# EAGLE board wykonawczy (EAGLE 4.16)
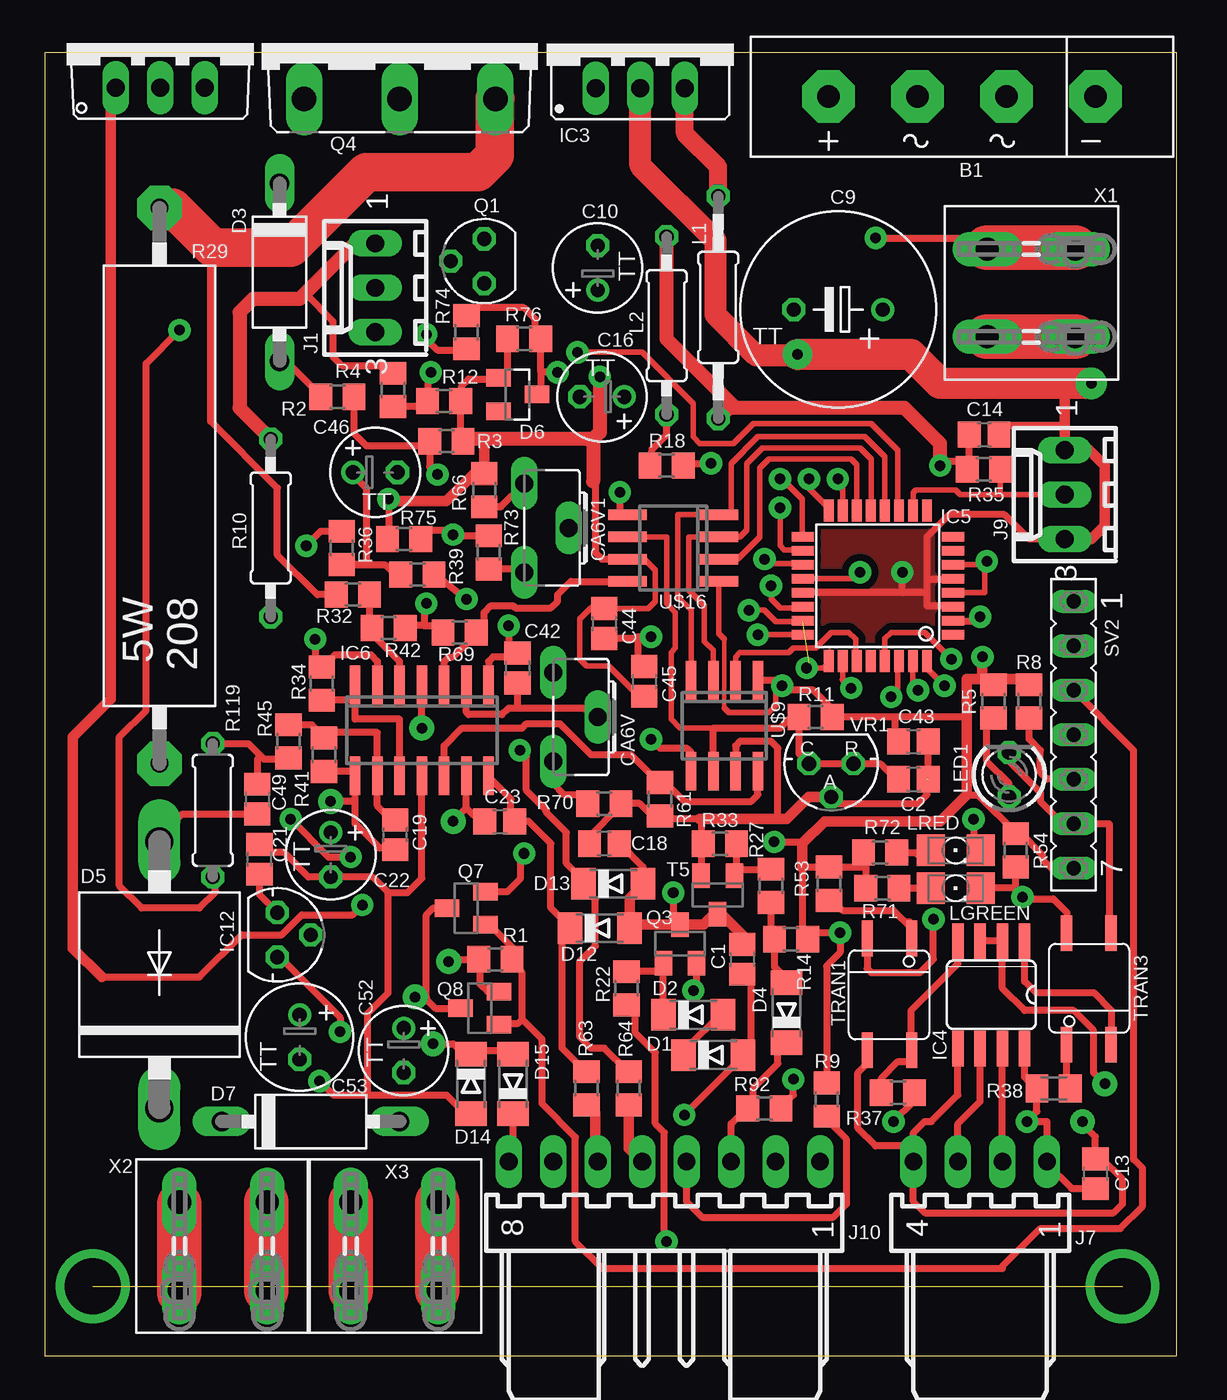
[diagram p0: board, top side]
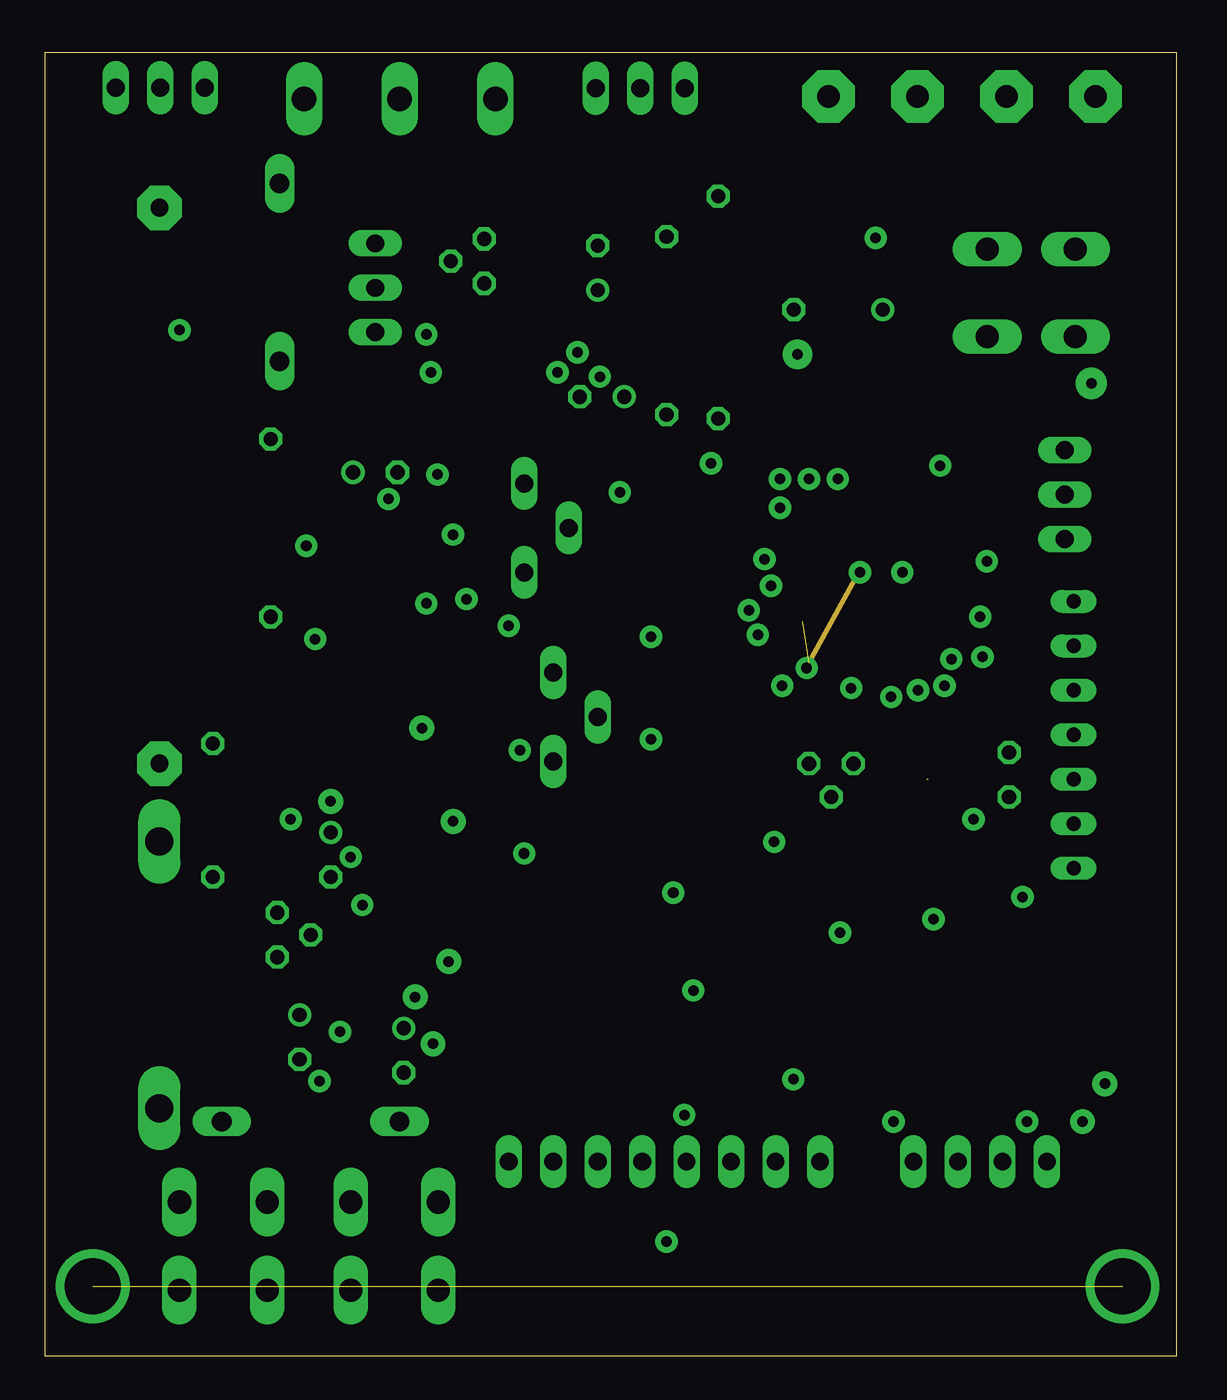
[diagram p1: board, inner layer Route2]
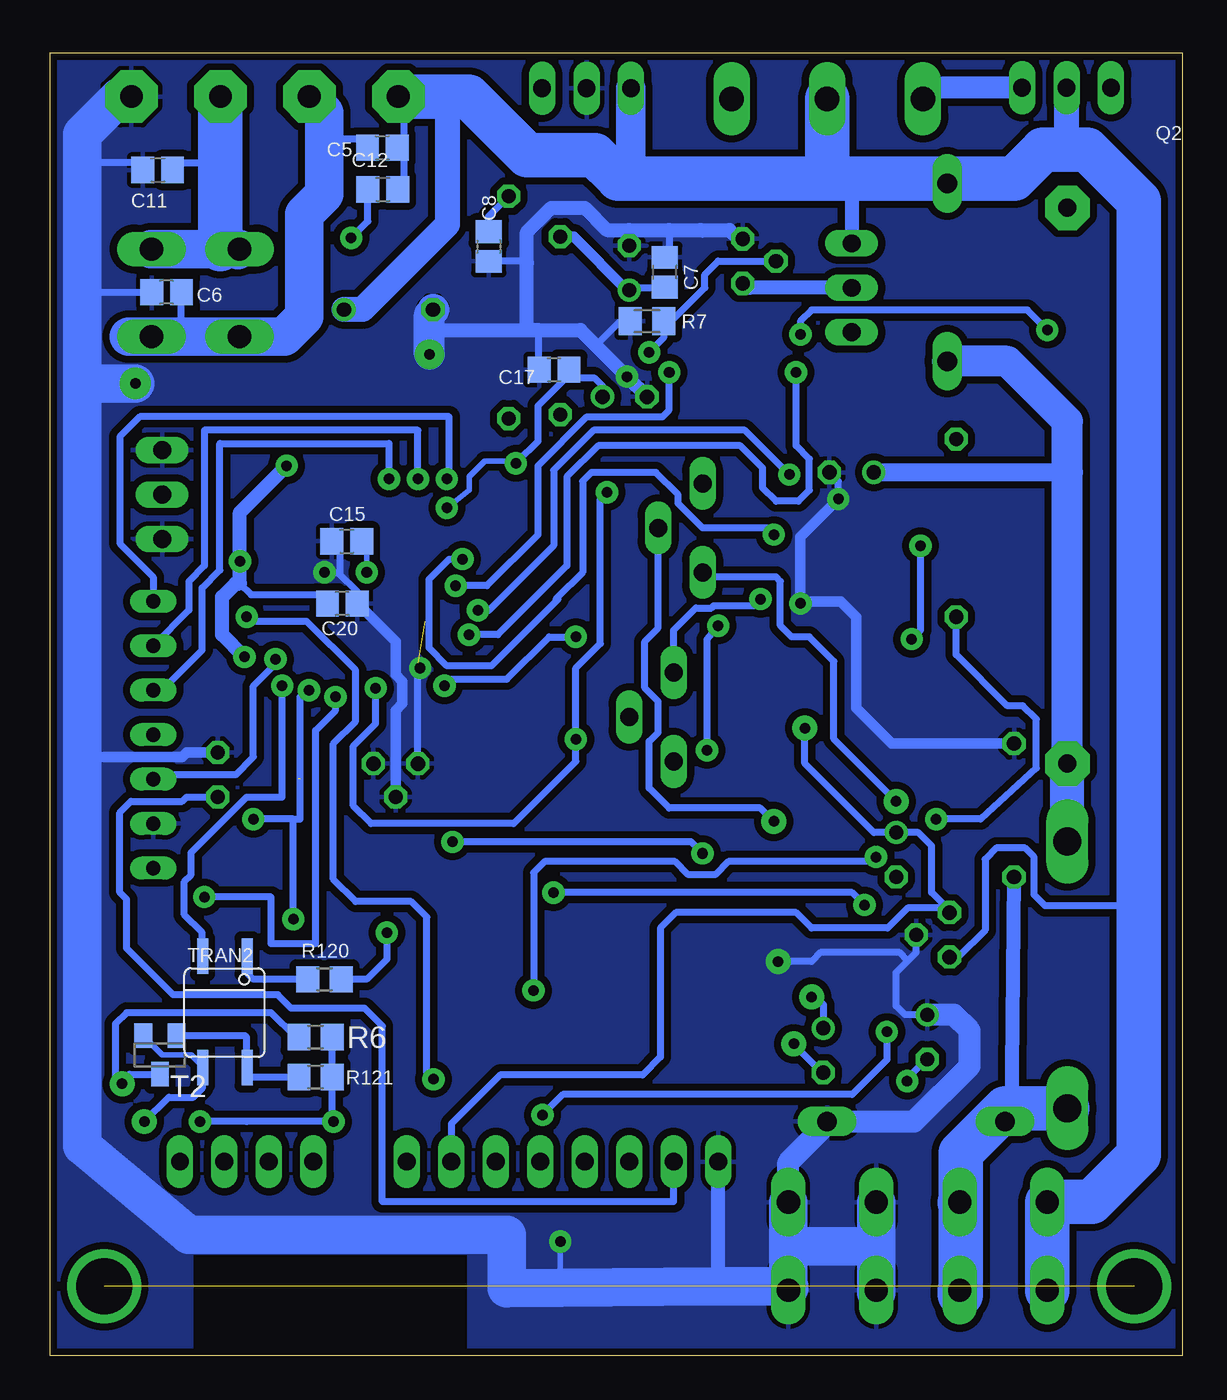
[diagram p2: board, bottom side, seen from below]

Size 64.62 x 74.42 mm. Coordinates in mm from the lower left corner, seen from the top.
Outline: 0,0 64.62,0 64.62,74.42 0,74.42 0,0
Copper layers (1*16): Top 0.035mm / dielectric 1.5mm / Bottom 0.035mm
Design rules "default": minimum track width 10mil, minimum drill 20mil, track to track 8mil, track to pad 8mil, pad to pad 8mil, via to via 8mil, smd to smd 8mil, copper to edge 1mil, drill to drill 8mil, minimum pad ring 10mil, minimum via ring 8mil, stop-mask expansion 4mil, vias tented up to drill 0mil, thermal gap 10mil

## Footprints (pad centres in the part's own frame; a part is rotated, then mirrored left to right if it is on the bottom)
2KBB_R2 = drill 1.3 pad 3 octagon: + -7.62,0; - 7.62,0; ~1 -2.54,0; ~2 2.54,0
C0805 = smd 1.3 x 1.5: 1 -0.85,0; 2 0.85,0
TT5D11 = drill 0.813 round: + -2.54,0 | drill 0.813 octagon: - 2.54,0
TT2D5 = drill 0.813 round: + -1.27,0 | drill 0.813 octagon: - 1.27,0
TT2D6 = drill 0.813 round: + -1.27,0 | drill 0.813 octagon: - 1.27,0
CA6H = drill 1.016 long: A -2.54,0; E 2.54,0; S 0,2.54
MINIMELF = smd 1.4 x 1.8: A 1.7,0; C -1.7,0
P1-10 = drill 1.118 long: A 5.08,0; C -5.08,0
P6-15 = drill 1.6 long: A 7.62,0; C -7.62,0
SOT23 = smd 1 x 1.4: 1 -0.95,-1.1; 2 0.95,-1.1; 3 0,1.1
78XXS = drill 1.016 long: GND 0,-2.54; IN -2.54,-2.54; OUT 2.54,-2.54
SO08 = smd 0.66 x 2.032: 1 -1.905,-3.073; 2 -0.635,-3.073; 3 0.635,-3.073; 4 1.905,-3.073; 5 1.905,3.073; 6 0.635,3.073; 7 -0.635,3.073; 8 -1.905,3.073
TQFP32-08 = smd 1.27 x 0.559: 1 -4.293,2.8; 2 -4.293,2; 3 -4.293,1.2; 4 -4.293,0.4; 5 -4.293,-0.4; 6 -4.293,-1.2; 7 -4.293,-2; 8 -4.293,-2.8; 17 4.293,-2.8; 18 4.293,-2; 19 4.293,-1.2; 20 4.293,-0.4; 21 4.293,0.4; 22 4.293,1.2; 23 4.293,2; 24 4.293,2.8 | smd 0.559 x 1.27: 9 -2.8,-4.293; 10 -2,-4.293; 11 -1.2,-4.293; 12 -0.4,-4.293; 13 0.4,-4.293; 14 1.2,-4.293; 15 2,-4.293; 16 2.8,-4.293; 25 2.8,4.293; 26 2,4.293; 27 1.2,4.293; 28 0.4,4.293; 29 -0.4,4.293; 30 -1.2,4.293; 31 -2,4.293; 32 -2.8,4.293
SO14 = smd 0.6 x 2.2: 1 -3.81,-2.6; 2 -2.54,-2.6; 3 -1.27,-2.6; 4 0,-2.6; 5 1.27,-2.6; 6 2.54,-2.6; 7 3.81,-2.6; 8 3.81,2.6; 9 2.54,2.6; 10 1.27,2.6; 11 0,2.6; 12 -1.27,2.6; 13 -2.54,2.6; 14 -3.81,2.6
78LXX = drill 0.813 octagon: GND 0,1.905; IN 1.27,0; OUT -1.27,0
6410-03 = drill 1.016 long: 1 2.54,0; 2 0,0; 3 -2.54,0
7395-04 = drill 1.016 long: 1 3.81,0; 2 1.27,0; 3 -1.27,0; 4 -3.81,0
7395-08 = drill 1.016 long: 1 8.89,0; 2 6.35,0; 3 3.81,0; 4 1.27,0; 5 -1.27,0; 6 -3.81,0; 7 -6.35,0; 8 -8.89,0
0207/12 = drill 0.813 octagon: 1 -6.35,0; 2 6.35,0
0207/10 = drill 0.813 octagon: 1 -5.08,0; 2 5.08,0
LED3MM = drill 0.813 octagon: A -1.27,0; K 1.27,0
1206 = smd 1.6 x 1.803: A -1.422,0; C 1.422,0
SOT54E = drill 0.813 octagon: D -1.27,0; G 0,1.905; S 1.27,0
TO220AV = drill 1.016 long: B -2.54,-2.54; C 0,-2.54; E 2.54,-2.54
TOP3AV = drill 1.397 long: B -5.461,-3.175; C 0,-3.175; E 5.461,-3.175
R0805 = smd 1.3 x 1.5: 1 -0.95,0; 2 0.95,0
M0805 = smd 1.3 x 1.6: 1 -0.95,0; 2 0.95,0
KH208-8 = drill 1.016 pad 2.54 octagon: 1 -15.875,0; 2 15.875,0
0207/7 = drill 0.813 octagon: 1 -3.81,0; 2 3.81,0
FE07 = drill 0.813 long: 1 -7.62,0; 2 -5.08,0; 3 -2.54,0; 4 0,0; 5 2.54,0; 6 5.08,0; 7 7.62,0
MFP4 = smd 2.032 x 0.635: 1 -3.226,1.295; 2 -3.226,-1.245; 3 3.15,-1.245; 4 3.15,1.295
SO-08 = smd 0.6 x 2.2: 1 -1.905,-2.6; 2 -0.635,-2.6; 3 0.635,-2.6; 4 1.905,-2.6; 5 1.905,2.6; 6 0.635,2.6; 7 -0.635,2.6; 8 -1.905,2.6
TO92-CLP = drill 0.813 octagon: A 0,1.905; C 1.27,0; R -1.27,0
SH5-2 = drill 1.321 long: 1 0,-2.515; 2 0,2.515; 3 5.004,-2.515; 4 5.004,2.515

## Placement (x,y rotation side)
B1  B600C8000  [2KBB_R2]  52.37,71.92 0 top
C1  10n  [C0805]  39.82,22.64 270 top
C2  1n  [C0805]  49.6,32.93 0 top
C5  100n  [C0805]  45.66,69 0 bottom
C6  100n  [C0805]  57.98,60.74 180 bottom
C7  100n  [C0805]  29.54,61.89 90 bottom
C8  100n  [C0805]  39.59,63.36 270 bottom
C9  1000u/25V  [TT5D11]  45.31,59.75 180 top
C10  100u  [TT2D5]  31.57,62.14 90 top
C11  100n  [C0805]  58.49,67.73 0 bottom
C12  100n  [C0805]  45.64,66.62 0 bottom
C13  100n  [C0805]  59.99,10.4 270 top
C14  100n  [C0805]  53.64,52.62 0 top
C15  1n  [C0805]  47.7,46.52 0 bottom
C16  4u7  [TT2D5]  31.82,54.78 180 top
C17  100n  [C0805]  35.86,56.32 0 bottom
C18  10n  [C0805]  31.95,29.25 180 top
C19  10n  [C0805]  20.01,29.76 90 top
C20  100n  [C0805]  47.95,42.96 180 bottom
C21  100n  [C0805]  12.26,28.36 90 top
C22  10u  [TT2D5]  16.33,28.61 270 top
C23  10n  [C0805]  25.98,30.52 0 top
C42  10n  [C0805]  27,39.28 270 top
C43  100n  [C0805]  49.6,35.09 0 top
C44  100n  [C0805]  31.95,41.82 270 top
C45  100n  [C0805]  34.23,38.52 270 top
C46  1u  [TT2D5]  18.87,50.46 0 top
C49  100n  [C0805]  12.14,31.79 270 top
C52  22u  [TT2D5]  20.49,17.44 270 top
C53  100u  [TT2D6]  14.55,18.2 270 top
CA6V  1k  [CA6H]  29.03,36.49 270 top
CA6V1  1k  [CA6H]  27.38,47.28 270 top
D1  BAV103  [MINIMELF]  38.17,17.18 0 top
D2  BAV103  [MINIMELF]  37.03,19.47 0 top
D3  1N4002  [P1-10]  13.41,61.89 270 top
D4  [MINIMELF]  42.36,19.6 90 top
D5  BY550  [P6-15]  6.55,21.76 90 top
D6  5v6  [SOT23]  27,54.9 270 top
D7  1N4002  [P1-10]  15.18,13.37 0 top
D12  BAS85  [MINIMELF]  31.69,24.42 0 top
D13  BAS85  [MINIMELF]  32.46,26.96 0 top
D14  BAS85  [MINIMELF]  24.33,15.53 270 top
D15  BAS85  [MINIMELF]  26.74,15.53 90 top
IC3  7805/T0220  [78XXS]  34.01,74.94 0 top
IC4  SN75176  [SO08]  54.05,20.61 180 top
IC5  ATMEGA8-16AU  [TQFP32-08]  47.57,43.98 180 top
IC6  TL084-SMD  [SO14]  21.53,35.73 180 top
IC12  78L24  [78LXX]  13.28,24.04 270 top
J1  zlacze NS25-W3P  [6410-03]  18.87,61 90 top
J7  zlacze NS25-W4K  [7395-04]  53.41,11.09 0 top
J9  zlacze NS25-W3P  [6410-03]  58.24,49.19 90 top
J10  zlacze NS25-W8K  [7395-08]  35.38,11.09 0 top
L1  1u/osiowy  [0207/12]  38.45,59.88 90 top
L2  100u/osiowy  [0207/10]  35.5,58.84 270 top
LED1  [LED3MM]  55.06,33.19 90 top
LGREEN  1206  [1206]  52.01,26.71 0 top
LRED  1206  [1206]  52.01,28.87 0 top
Q1  BS170  [SOT54E]  25.09,62.52 90 top
Q2  BD243  [TO220AV]  6.6,74.97 0 top
Q3  BCW67C  [SOT23]  36.27,23.53 0 top
Q4  BD245  [TOP3AV]  20.26,74.97 0 top
Q7  BSS84  [SOT23]  24.07,25.57 90 top
Q8  BSS123  [SOT23]  24.84,19.85 90 top
R1  100k  [R0805]  25.73,22.64 180 top
R2  4k7  [R0805]  16.71,54.78 180 top
R3  560  [R0805]  22.93,52.24 180 top
R4  4k7  [R0805]  19.88,55.16 270 top
R5  470  [R0805]  54.17,37.38 270 top
R6  1k  [R0805]  49.47,18.2 180 bottom
R7  100k  [M0805]  30.55,59.09 180 bottom
R8  10k  [R0805]  56.21,37.38 90 top
R9  1k  [R0805]  44.65,14.64 90 top
R10  56  [0207/10]  12.9,47.28 90 top
R11  470  [R0805]  44.01,36.49 0 top
R12  330  [R0805]  22.8,54.52 0 top
R14  1k  [R0805]  42.62,23.79 0 top
R18  1R5  [R0805]  35.5,50.84 0 top
R22  10k  [R0805]  33.22,20.99 270 top
R27  2k2  [R0805]  41.47,26.84 270 top
R29  0.56/5W  [KH208-8]  6.55,49.7 270 top
R32  3k3/1%  [R0805]  17.6,43.47 180 top
R33  1k  [R0805]  38.55,29.25 0 top
R34  1k5/1%  [R0805]  15.82,38.39 270 top
R35  4k7  [R0805]  53.61,50.64 180 top
R36  3k3/1%  [R0805]  16.96,46.14 90 top
R37  1k  [R0805]  48.71,15.02 180 top
R38  330  [M0805]  57.6,15.28 0 top
R39  10k  [R0805]  21.28,44.62 180 top
R41  3k9/1%  [R0805]  15.95,34.33 90 top
R42  1k5/1%  [R0805]  19.63,41.57 180 top
R45  1k5/1%  [R0805]  13.91,35.09 270 top
R53  1k1  [R0805]  44.78,26.96 270 top
R54  1k  [R0805]  55.44,28.87 270 top
R61  4k7  [R0805]  35.12,31.79 90 top
R63  10k  [R0805]  30.93,15.28 90 top
R64  10k  [R0805]  33.35,15.28 90 top
R66  3k9  [R0805]  25.09,49.44 90 top
R69  4k7  [R0805]  23.69,41.31 0 top
R70  1k  [R0805]  31.95,31.53 180 top
R71  470  [R0805]  47.82,26.71 0 top
R72  470  [R0805]  47.7,28.74 0 top
R73  1k5  [R0805]  25.34,45.89 90 top
R74  4k7  [R0805]  24.07,58.46 270 top
R75  5k6  [R0805]  20.52,46.65 0 top
R76  560  [R0805]  27.38,58.08 0 top
R92  100  [R0805]  41.09,14.14 180 top
R119  1k5  [0207/7]  9.6,31.15 270 top
R120  1k  [R0805]  48.97,21.5 180 bottom
R121  10k  [R0805]  49.47,15.91 180 bottom
SV2  [FE07]  58.75,35.47 270 top
T2  BC847  [SOT23]  58.36,17.18 180 bottom
T5  BCX41  [SOT23]  38.43,26.33 180 top
TRAN1  PC357Z  [MFP4]  48.2,20.61 270 top
TRAN2  PC357Z  [MFP4]  54.68,19.6 270 bottom
TRAN3  PC357Z  [MFP4]  59.63,20.99 90 top
U$9  MCP4921  [SO-08]  38.81,35.98 180 top
U$16  MCP4921  [SO-08]  35.89,46.14 90 top
VR1  TL431/TO92  [TO92-CLP]  44.9,33.82 180 top
X1  zlacze LST1407  [SH5-2]  56.33,58.2 90 top
X2  zlacze LST1407  [SH5-2]  7.69,6.26 0 top
X3  zlacze LST1407  [SH5-2]  17.47,6.26 0 top

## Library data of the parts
B1 = rectifier
C1 C2 C5-C23 C42-C46 C49 C52 C53 L1 L2 R1-R12 R14 R18 R22 R27 R32-R39 R41 R42 R45 R53 R54 R61 R63 R64 R66 R69-R76 R92 R119-R121 = rcl
CA6V CA6V1 = pot
D1-D7 D12-D15 = diode
IC3 IC12 VR1 = v-reg
IC4 = maxim
IC5 = atmel
IC6 = linear
J1 J7 J9 J10 = con-molex
LED1 LGREEN LRED = led
Q1 Q7 Q8 = transistor-small-signal
Q2 Q4 = transistor-power
Q3 = transistor-pnp
R29 = resistor-power
SV2 = con-lsta
T2 T5 = transistor
TRAN1-TRAN3 = optocoupler
U$9 U$16 = microchip
X1-X3 = con-rib

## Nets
+5V: C7.1 C10.+ C14.1 C20.2 C43.1 C44.2 C45.1 IC5.4 IC5.6 L1.1 L2.1 Q7.2 R5.1 R8.2 R9.2 R11.2 R14.2 R35.2 R53.1 R54.1 R71.1 R72.1 R120.1 SV2.7 U$9.1 U$16.1
+24V: C21.1 C22.+ IC6.4 IC12.OUT J10.2
-5V: C21.2 C22.- C53.- D14.A IC6.11
A: IC4.6 J7.3
ADC6: IC5.19 R73.2 R75.2
ADC7: D6.3 IC5.22 R74.1 R76.2
AVCC: C16.+ C17.2 IC5.18 R18.2
B: IC4.7 J7.2
CS1: IC5.14 U$16.2
CS2: IC5.27 U$9.2
GND: B1.- C2.1 C2.2 C6.2 C7.2 C8.2 C9.- C10.- C11.1 C14.2 C15.1 C16.- C17.1 C18.2 C20.1 C43.2 C44.1 C45.2 C46.- C49.1 C53.+ D6.1 D7.A D15.C IC3.GND IC5.3 IC5.5 IC5.21 IC5.25 IC12.GND J9.1 J9.3 J10.8 LED1.K Q1.S Q8.2 R1.2 R3.1 R7.2 R11.1 R12.2 R22.2 R33.1 R42.1 R45.2 R61.1 R66.2 R69.1 R70.1 R75.1 R76.1 R119.1 SV2.6 T5.2 TRAN3.3 U$9.6 U$9.7 U$16.6 U$16.7 VR1.A VR1.C VR1.R X3.1 X3.2 X3.3 X3.4
GND_RS485: C13.1 IC4.5 J7.4 T2.2 TRAN1.3 TRAN2.3
IOUT: IC6.12 R61.2 U$9.8
LDAC: IC5.26 U$9.5 U$16.5
MISO: IC5.16 SV2.2
MOSI: IC5.15 Q7.1 Q8.1 R1.1 SV2.3
N$1: CA6V.A R39.1
N$2: IC6.6 R34.1 R36.2
N$3: C42.2 CA6V.S IC6.2
N$4: IC6.5 R32.1 R42.2
N$5: IC6.7 IC6.10 R34.2
N$6: C23.1 CA6V1.S IC6.13
N$7: C19.2 IC6.9 R41.2 R45.1
N$8: C19.1 CA6V1.E IC6.8 R41.1 R73.1
N$10: C1.1 C18.1 D12.A D13.A Q2.B Q3.3 T5.3
N$11: R120.2 TRAN2.1
N$12: IC5.32 TRAN2.2
N$14: CA6V.E R70.2
N$16: C23.2 D12.C IC6.14 R63.2
N$17: CA6V1.A R66.1
N$19: Q4.E R29.1 R32.2
N$22: D4.A R14.1 R27.2
N$23: D1.C D2.A
N$25: R27.1 R33.2 T5.1
N$28: Q2.E Q4.B
N$33: C52.+ Q7.3 Q8.3
N$34: IC4.4 R37.2 TRAN1.4
N$35: IC5.10 J9.2 R35.1
N$36: D2.C Q3.1 R22.1
N$37: J10.6 R63.1
N$38: J10.5 R64.1
N$39: IC5.23 R2.1 R3.2
N$40: C46.+ C49.2 D3.A D5.A R2.2 R29.2 R36.1 R39.2
N$42: C52.- D14.C D15.A
N$43: L2.2 R18.1
N$44: R53.2 TRAN1.1
N$45: IC4.1 TRAN3.2
N$47: IC5.24 R4.2 R12.1
N$54: R38.2 TRAN3.1
N$55: R121.2 T2.1 TRAN2.4
N$56: C8.1 IC3.OUT L1.2
N$57: J10.7 LED1.A R5.2
N$59: D5.C D7.C R74.2 R119.2 X2.3 X2.4
N$60: C42.1 D13.C IC6.1 R64.2
N$64: LRED.A R72.2
N$65: IC4.2 IC4.3 R6.2 T2.3
N$66: LGREEN.A R71.2
N$67: Q3.2 R10.1
N$68: B1.~2 C11.2 C12.1 X1.3 X1.4
N$69: B1.~1 C5.1 C6.1 X1.1 X1.2
N$100: D4.C J10.3 R92.2
N$112: J1.2 Q1.D
N$115: IC5.11 Q1.G R7.1
N$125: C15.2 IC5.20
N$144: J10.4 R9.1
RST: IC5.29 R8.1 SV2.5
RXD: IC5.30 LGREEN.C R54.2 TRAN3.4
SCK: IC5.17 SV2.1
SCK_DA: IC5.13 U$9.3 U$16.3
SDI: IC5.12 U$9.4 U$16.4
TXD: IC5.31 LRED.C TRAN1.2
V+: B1.+ C1.2 C5.2 C9.+ C12.2 D1.A D3.C IC3.IN IC12.IN J1.1 Q2.C Q4.C R4.1 R10.2 X2.1 X2.2
VCC_RS485: C13.2 IC4.8 J7.1 R6.1 R37.1 R38.1 R121.1
VOUT: IC6.3 R69.2 U$16.8
ZAS_ON_OFF: IC5.2 R92.1

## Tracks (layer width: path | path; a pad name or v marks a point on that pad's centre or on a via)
+5V  (via drill 0.6 pad 1.27)
  Top 0.254: 38.81,37 38.81,40.93
  Top 0.305: U$16.1 38.49,41.25 38.81,40.93 | 33.85,40.93 33.81,40.97 | 38.81,37 39.06,36.74 41.35,36.74 41.73,37.12 41.73,37.88 v42.11,38.27 | IC5.6 51.96,45.18 52.01,45.12 52.07,45.18 53.67,45.18 | 51.89,43.58 51.89,43.47 | 51.89,43.58 IC5.4 | 51.89,43.58 51.89,43.6 53.67,43.6 53.67,45.18 | 53.67,45.18 53.6,45.18 v53.79,45.38 | R54.1 55.7,30.14
  Top 0.406: 52.78,53 53.16,52.62 C14.1 52.79,50.9 52.9,50.97 | 33.81,40.97 C44.2 | 33.85,39.92 33.85,39.79 34.23,39.41 C45.1 34.23,39.54 33.85,39.92 | 33.85,39.92 33.85,40.93 33.85,41.06 v34.62,41.06 | R35.2 52.92,50.65 52.9,50.97 | 52.9,50.97 52.78,51.09 51.38,51.09 v51.13,50.84 | 41.73,38.58 U$9.1 | 41.73,38.58 v42.11,38.27 | 41.73,38.58 41.73,38.52 42.24,38.01 43.89,38.01 44.71,37.19 | SV2.7 57.48,27.85 56.97,28.36 56.97,28.61 55.7,29.88 55.63,29.82 R54.1 55.51,29.82 | 45.28,36.64 R11.2 44.96,36.93 44.71,37.19 | R8.2 56.14,38.33 56.08,38.27 55.7,38.65 54.81,38.65 54.49,38.33 R5.1 | Q7.2 26.42,26.52 27.17,27.27 27.17,28.49 v27.38,28.69 | C43.1 48.55,35.18 48.55,36.4 48.46,36.49 | 44.71,37.19 44.65,37.12 45.28,36.49 48.46,36.49 | 55.7,30.14 55.57,30.14 | 55.51,29.82 55.57,29.76 | R72.1 46.87,28.55 46.93,28.49 46.68,28.23 | R71.1 46.87,28.04 46.68,28.23 | 55.51,29.82 53.28,32.04 52.65,32.04 | 52.65,36.49 48.46,36.49 | 46.68,28.23 46.61,27.91 R53.1 43.31,27.91 43.31,28.04 | v41.65,29.35 43.33,29.35 43.29,29.29 | 43.31,28.04 43.25,27.72 | 43.31,28.04 43.25,27.85 43.25,24.17 43.57,23.85 R14.2 43.57,23.98 43.51,24.04 43.63,24.17 v45.41,24.17 45.41,23.03 44.65,22.26 R9.2
  Top 0.61: 56.08,38.52 56.21,38.39 R8.2 | 53.54,38.65 55.7,38.65 | 53.54,38.65 R5.1 | 53.54,38.65 v53.54,39.92 | 53.54,38.65 52.65,38.65 52.65,36.49 52.65,32.04 51.13,30.52 44.52,30.52 43.29,29.29 43.25,29.25 43.25,27.85
  Top 0.813: L2.1 35.5,58.08 39.25,54.33 | 39.25,54.33 L1.1 | 39.44,54.14 39.31,54.14 | 39.44,54.14 39.25,54.33 | 39.44,54.14 49.09,54.14 51.13,52.11 v51.13,50.84
  Bottom 0.406: C7.1 29.5,61.04 29.41,61 31.44,61 C10.+ | v34.62,41.06 36.14,41.06 38.55,38.65 41.73,38.65 v42.11,38.27 | C20.2 48.8,43.18 49.09,43.47 53.16,43.47 53.79,44.11 | v27.38,28.69 28.04,29.35 v41.65,29.35 | 48.02,21.31 R120.1 46.55,21.5 45.41,22.64 v45.41,24.17
  Bottom 0.61: C10.+ 31.69,60.87 34.74,63.92 L2.1
  Bottom 0.813: v51.13,50.84 53.79,48.17 v53.79,45.38 53.79,44.11 54.05,44.11 54.81,43.35 54.81,41.19 v53.54,39.92
+24V  (via drill 0.6 pad 1.42)
  Top 0.406: v21.53,35.85 IC6.4 | C21.1 12.26,26.33 IC12.OUT
  Bottom 0.406: v21.53,35.85 21.53,33.82 17.6,29.88 C22.+ 15.06,29.88 14.3,29.12 14.3,26.45 13.28,25.44 IC12.OUT 13.53,25.57 15.67,25.57 16.81,24.42 21.15,24.42 22.04,25.31 28.9,25.31 29.79,24.42 29.79,17.06 30.81,16.04 38.93,16.04 41.73,13.25 J10.2
-5V  (via drill 0.6 pad 1.27)
  Top 0.406: C22.- 16.29,27.38 | C21.2 12.3,29.21 12.77,28.74 13.66,28.74 15.06,27.34 C22.- | D14.A 24.2,13.63 22.93,14.9 18.44,14.9 | 18.44,14.9 16.48,14.9 v15.69,15.68 | C22.- 18.72,27.34 19.6,26.45 | 19.6,26.45 19.6,20.71 18.44,19.55 18.44,14.9 | IC6.11 21.53,27.27 20.72,26.45 19.6,26.45
  Bottom 0.406: C53.- 14.57,16.95 15.69,15.84 v15.69,15.68
A
  Top 0.406: IC4.6 53.41,14.52 52.14,13.25 J7.3
ADC6  (via drill 0.6 pad 1.27)
  Top 0.305: IC5.19 43.07,45.18 43,45.25 41.35,45.25 v41.09,45.5
  Top 0.406: R75.2 21.47,46.71 21.92,47.16 23.06,47.16 v23.31,46.9 23.38,46.84 R73.2
  Bottom 0.406: v23.31,46.9 23.69,47.28 27.38,47.28 28.77,48.68 28.77,49.19 30.04,50.46 33.73,50.46 34.23,49.95 34.23,44.74 35.69,43.28 | 35.69,43.28 35.76,43.22 | v41.09,45.5 41.85,45.5 43,44.36 43,40.42 41.98,39.41 39.44,39.41 35.63,43.22 35.69,43.28
ADC7  (via drill 0.6 pad 1.27)
  Top 0.254: 28.39,58.33 28.39,58.36 R76.2
  Top 0.305: v41.47,43.98 41.47,43.22 41.98,42.71 43.12,42.71 43.19,42.78 IC5.22
  Top 0.406: D6.3 28.39,54.9 28.33,55.22 28.33,56.17 | 28.33,56.17 R76.2 28.14,58.08 28.01,58.2 28.01,59.22 27.38,59.86 24.52,59.86 R74.1 | 28.39,58.33 28.33,58.27 | 43,42.71 43.07,42.78 IC5.22 | v29.28,56.17 28.33,56.17
  Bottom 0.406: v29.28,56.17 29.28,54.01 29.66,53.63 33.98,53.63 36.77,50.84 36.77,46.9 39.7,43.98 v41.47,43.98
AVCC  (via drill 0.6 pad 1.27)
  Top 0.305: 43.25,46.01 IC5.18 43.28,45.91 43.25,45.89 43.12,46.01 42.24,46.01 41.98,46.27 v41.98,48.43
  Top 0.406: R18.2 36.58,50.78 36.65,50.97 v38.04,50.97
  Bottom 0.305: 37.92,51.09 39.82,51.09 40.71,50.2 40.71,49.44 v41.98,48.43
  Bottom 0.406: v38.04,50.97 37.92,51.09 36.77,52.24 36.77,54.27 36.75,54.27 34.84,56.17 35,56.32 C17.2 | C17.2 35.25,55.92 | C16.+ 33.09,55.38 33.57,55.87 34.49,55.87 34.95,56.32 C17.2
B
  Top 0.406: J7.2 IC4.7
CS1
  Top 0.305: IC5.14 46.37,50.9 46.05,51.22 41.35,51.22 40.84,50.71 40.84,46.77 39.57,45.5 U$16.2
  Top 0.406: U$16.2 38.43,45.5
CS2
  Top 0.305: U$9.2 39.44,39.92 39.7,40.17 42.49,40.17 42.74,40.42 44.01,40.42 44.9,41.31 45.92,41.31 46.3,40.93 46.3,39.92 46.43,39.79 46.37,39.73 IC5.27
GND  (via drill 0.6 pad 1.27, 0.6 pad 1.42, 0.6 pad 1.68, 0.6 pad 1.78)  (1 unrouted)
  Top 0.254: R33.1 37.28,29.5 37.48,29.7
  Top 0.305: 51.76,44.36 51.76,44.38 IC5.5 | 31.15,42.67 30.55,42.08 30.55,39.79 30.93,39.41 32.2,39.41 33.98,37.63 | C44.1 34.45,42.67 34.87,43.09 34.87,44.87 34.23,45.5 U$16.7 | U$16.6 35.5,46.77 35.5,42.96 36.01,42.46 36.01,40.42 35.76,40.17 35.76,36.36 36.27,35.85 38.3,35.85 | v43.51,39.28 44.52,39.28
  Top 0.406: TRAN3.3 60.88,24.57 60.78,24.55 60.78,30.39 SV2.6 58.11,30.39 56.84,31.66 56.84,32.17 55.06,33.95 LED1.K | Q8.2 25.28,20.8 24.84,21.25 24.84,22.26 24.46,22.64 | 24.46,22.64 R1.2 | 24.46,22.64 23.19,22.64 v23.06,22.52 | C43.2 50.62,35.09 50.45,34.92 C2.2 | 50.11,32.68 50.36,32.93 50.36,32.04 49.86,31.53 45.16,31.53 44.78,31.92 | U$9.7 39.44,34.84 39.7,35.09 41.47,35.09 41.85,34.71 41.85,30.65 | 50.36,43.6 50.36,42.84 51.89,42.84 51.89,42.78 IC5.3 | 48.97,43.58 50.36,43.58 50.36,43.6 | 48.97,43.58 IC5.21 | 48.97,43.58 v48.97,44.74 | U$16.7 31.82,45.5 31.44,45.89 31.44,49.82 31.38,49.89 | 37.48,29.7 T5.2 | 37.48,29.7 37.54,29.76 | 31.31,49.95 31.38,49.89 | 31.38,49.89 31.31,49.82 | R76.1 26.43,56.24 26.11,55.92 26.17,55.85 D6.1 26.3,55.85 26.36,55.79 24.2,55.79 23.82,55.41 23.82,54.78 23.75,54.71 R12.2 23.75,52.81 24.2,52.36 24.07,52.24 R3.1 23.88,52.17 23.95,52.11 | R75.1 19.57,46.71 19.63,46.77 v19.63,48.93 | 37.48,29.7 37.48,30.45 37.41,30.52 37.41,30.65 35.25,30.65 35.12,30.77 R61.1 34.81,30.84 34.74,30.77 33.98,31.53 R70.1 32.9,31.47 30.93,29.5 31.1,29.34 C18.2 | 50.36,44.36 50.36,46.77 51.63,48.04 54.81,48.04 56.21,46.65 J9.3 | 50.36,44.36 50.36,43.6 | C14.2 54.44,52.7 54.86,53.12 58.11,53.12 58.24,53 | 50.36,44.36 51.76,44.36 | C44.1 31.15,42.67 | 33.98,37.63 34.02,37.67 C45.2 | R42.1 20.77,41.57 20.9,41.69 21.66,41.69 | R69.1 22.74,41.37 22.42,41.69 21.66,41.69 | 21.66,41.69 21.66,42.84 v21.79,42.96 | 12.33,34.26 12.52,34.07 13.91,34.07 R45.2 | C49.1 12.14,34.07 12.33,34.26 | R22.2 33.28,20.04 33.73,19.6 33.73,18.45 34.87,17.31 34.87,13.25 35.38,12.74 35.38,6.77 v35.5,6.52
  Top 0.406: 44.78,31.92 44.65,32.04 | VR1.A 44.78,31.92 | J10.8 26.49,10.96 26.74,11.21 D15.C | R119.1 11.63,34.96 12.33,34.26 | U$9.6 38.17,35.85 38.3,35.85 41.98,35.85 42.87,36.74 R11.1 43.06,34.39 VR1.C VR1.R | 48.59,32.93 48.33,32.93 | 44.52,39.28 44.78,39.41 44.78,39.66 44.77,39.67 IC5.25 | VR1.R 46.3,33.69 | 48.59,32.93 C2.1 | VR1.R 47.7,33.82 48.59,32.93
  Top 0.61: J9.1 58.11,51.73 | J9.1 59.63,51.73 60.52,50.84 60.52,47.41 59.76,46.65 J9.3 | J9.1 58.24,51.6 | v59.76,55.54 58.24,55.54 58.24,53 J9.1 | R3.1 23.88,52.3 23.95,52.36 24.2,52.36 | VR1.A 43.63,31.92 42.36,30.65 41.85,30.65 37.41,30.65 | 32.84,31.92 32.9,31.98 R70.1 | 24.52,50.39 R66.2 | 24.52,50.39 22.93,48.81 19.76,48.81 v19.63,48.93 | 24.52,50.39 24.77,50.39 25.09,50.71 25.09,52.36
  Top 0.813: 31.31,49.95 31.31,52.36 31.19,52.36 | 31.19,52.36 25.09,52.36 24.2,52.36 | 31.19,52.36 31.19,52.24 31.69,52.74 v31.69,55.92
  Top 1.27: IC3.GND 34.01,67.98 38.3,63.69 38.3,59.47 40.64,57.14 42.97,57.14 v42.97,57.19
  Top 1.778: v59.76,55.54 51.13,55.54 49.47,57.19 v42.97,57.19
  Bottom 0.305: C15.1 48.59,46.52 48.08,46.01 48.08,45.89 | 35.5,3.88 35.5,3.98 v35.5,6.52
  Bottom 0.406: C6.2 62.94,60.74 62.81,60.62 | 15.65,22.56 16.33,21.88 16.33,19.98 15.82,19.47 C53.+ | 15.65,22.56 15.18,23.03 IC12.GND | v23.06,22.52 21.15,22.52 20.65,23.03 16.12,23.03 15.65,22.56 | C7.2 29.5,62.74 29.28,63.16 29.28,64.3 | 27.5,64.3 27.5,64.17 27.38,64.05 | C15.1 48.55,46.35 48.84,46.35 48.84,46.9 | 48.08,45.89 48.08,44.74 48.2,44.74 | 62.81,36.74 63.06,36.74 | v48.97,44.74 48.2,44.74 | C17.1 36.77,56.08 36.77,58.59 | C46.- 19.63,49.95 v19.63,48.93 | C20.1 47.1,43.64 48.2,44.74 | v21.79,42.96 21.66,43.09 | R7.2 32.08,59.09 33.47,57.7 | 37.41,62.42 37.54,62.42 37.63,62.51 C8.2 | C11.1 59.36,67.73 59.79,68.16 62.81,68.16 62.89,68.16 | VR1.C 43.63,39.15 v43.51,39.28
  Bottom 0.61: 26.61,3.98 26.61,3.85 26.49,3.98 | LED1.K 56.84,34.46 57.09,34.2 62.81,34.2 | C20.1 47.06,42.96 44.9,40.81 44.9,38.9 44.52,38.52 44.52,37.25 44.9,36.87 VR1.A | v21.79,42.96 21.79,46.77 v19.63,48.93 | 21.66,43.09 19.5,43.09 18.61,42.2 18.61,37 16.58,34.96 R119.1
  Bottom 0.813: Q1.S 25.34,63.79 25.85,64.3 27.5,64.3 29.28,64.3 31.57,64.3 | 31.57,64.3 C10.- | 31.57,64.3 32.84,64.3 34.11,65.57 36.01,65.57 37.41,64.17 37.41,62.42 37.41,58.59 37.43,58.56 37.43,58.59 36.77,58.59 | 36.77,58.59 34.36,58.59 33.47,57.7 v31.69,55.92 | v31.69,55.92 C16.- v31.69,55.92 | 26.61,3.98 26.61,4.1 26.49,4.23 26.49,10.96 | 42.97,58.61 42.92,58.61 42.9,58.59 36.77,58.59
  Bottom 1.27: X3.4 22.47,11.04 20.14,13.37 D7.A 15.31,13.37 12.14,16.55 12.14,18.58 13.03,19.47 C53.+
  Bottom 1.778: C9.- 42.74,59.75 42.72,59.73 42.97,59.47 42.97,58.61 v42.97,57.19
  Bottom 2.184: 62.81,55.54 62.81,36.74 62.81,34.2 62.81,11.98 56.71,6.9 38.55,6.9 38.55,3.85 35.5,3.88 26.61,3.98 26.49,3.98 22.55,3.98 22.42,3.85 22.47,3.8 X3.3 22.47,3.92 22.42,3.98 22.47,4.03 X3.4 22.47,6.31 22.42,6.26 17.47,6.26 | 62.81,55.54 62.81,60.62 62.81,68.16 62.81,69.76 60.65,71.92 B1.- | 17.47,3.59 X3.1 17.47,6.26 | 17.47,6.26 X3.2 | 62.81,55.54 v59.76,55.54
  pour Bottom (isolate 0.406): 0.07,74.33 64.59,74.46 64.59,0.04 56.59,0.04 56.59,5.88 40.71,5.88 40.71,0.17 0.07,0.04
  pour Top (isolate 0.406): 44.01,47.41 51,47.41 51,40.42 44.01,40.42
GND_RS485  (via drill 0.6 pad 1.42)
  Top 0.406: 46.96,17.34 46.96,17.08 | 46.96,17.34 46.93,17.31 46.93,16.68 46.43,16.17 46.43,12.99 47.44,11.98 49.6,11.98 | 46.96,17.34 TRAN1.3 | IC4.5 52.14,14.9 50.62,13.37 50.24,13.37 49.6,12.74 49.6,11.98 | v59.25,13.37 59.25,13.25 59.99,12.51 C13.1 60.36,11.25 61.54,10.07 61.54,8.67 61.03,8.17 50.24,8.17 49.6,8.8 49.6,10.83 | 49.6,10.83 J7.4 | 49.6,10.83 49.6,11.98
  Bottom 0.305: 59.31,18.26 58.24,17.18 56.59,17.18 55.93,16.52
  Bottom 0.406: 59.31,18.26 T2.2 | 55.93,16.52 TRAN2.3 55.93,15.3 56.46,14.77 57.86,14.77 v59.25,13.37
IOUT
  Top 0.406: U$9.8 40.71,32.04 40.33,31.66 36.52,31.66 35.38,32.8 35.31,32.74 R61.2 35.12,32.68 33.47,34.33 31.19,34.33 29.41,36.11 27.5,36.11 27.25,35.85 23.82,35.85 22.8,34.84 IC6.12
LDAC  (via drill 0.6 pad 1.27)
  Top 0.305: 45.57,38.61 IC5.26
  Top 0.406: U$9.5 36.9,34.46 36.65,34.71 35.12,34.71 v34.62,35.22 | v32.84,49.31 32.84,48.04 U$16.5 | v46.05,38.14 45.57,38.61
  Bottom 0.406: v32.84,49.31 33.22,48.93 33.22,40.68 34.62,39.28 v34.62,35.22 34.62,33.95 38.17,30.39 46.3,30.39 47.32,31.41 47.32,34.84 46.05,36.11 v46.05,38.14
MISO  (via drill 0.6 pad 1.27)
  Top 0.305: IC5.16 | v43.63,50.08 43.63,49.57 44.78,48.43
  Top 0.406: 44.78,48.43 44.77,48.42 IC5.16
  Bottom 0.406: v43.63,50.08 43.63,52.87 55.82,52.87 55.82,45.12 56.71,44.23 56.71,42.58 SV2.2
MOSI  (via drill 0.6 pad 1.27)
  Top 0.305: 45.16,50.33 v45.28,50.08 45.57,50.08 IC5.15
  Top 0.406: 27.25,19.22 27.25,21.88 26.49,22.64 R1.1 26.68,22.71 26.74,22.77 26.74,23.28 25.41,24.62 Q7.1 | 27.25,19.22 27,18.96 26.11,18.96 26.05,18.9 Q8.1 | SV2.3 62.17,34.58 62.17,11.21 62.68,10.71 62.68,8.55 61.41,7.28 56.84,7.28 54.68,5.12 54.68,4.99 31.82,4.99 30.3,6.52 30.3,12.48 28.39,14.39 28.39,18.07 27.25,19.22
  Bottom 0.254: 58.24,38.01 58.87,38.39 SV2.3
  Bottom 0.406: v45.28,50.08 45.28,52.11 54.94,52.11 54.94,44.87 55.95,43.85 55.95,40.3 58.24,38.01
N$1  (via drill 0.6 pad 1.27)
  Top 0.406: 22.55,45 22.23,44.68 R39.1 22.3,44.62 v24.07,43.22
  Bottom 0.406: v24.07,43.22 24.46,42.84 26.74,42.84 26.87,42.71 27.76,42.71 29.03,41.44 29.03,39.15 28.9,39.03 CA6V.A
N$2  (via drill 0.6 pad 1.27)
  Top 0.406: IC6.6 18.99,39.66 18.61,40.04 16.58,40.04 15.88,39.34 R34.1 | R34.1 15.82,39.28 | 16.84,47.16 16.96,47.03 R36.2 15.75,47.09 v14.93,46.27 | R34.1 15.82,39.41 15.44,39.79 | R34.1 15.76,39.34 15.44,39.66 v15.44,40.93
  Bottom 0.406: v14.93,46.27 14.93,41.44 v15.44,40.93
N$3
  Top 0.406: IC6.2 24.07,36.74 24.2,36.61 26.11,36.61 26.49,37 26.87,37 | CA6V.S 31.31,36.49 30.81,37 26.87,37 | C42.2 27,37.12 26.87,37
N$4
  Top 0.406: IC6.5 20.26,39.66 18.43,41.5 R42.2 18.74,41.57 | 18.74,41.57 18.87,41.44 | R32.1 18.55,41.76 18.74,41.57
N$5
  Top 0.406: 17.54,37.44 R34.2 | 17.54,37.44 17.72,37.38 IC6.7 | IC6.10 20.26,36.36 17.72,36.36 17.72,37 17.79,37.44 17.54,37.44
N$6  (via drill 0.6 pad 1.42)
  Top 0.406: 25.47,30.14 25.09,30.52 C23.1 25.13,30.86 24.49,30.86 24.07,31.28 | 24.07,31.28 IC6.13 | 24.07,31.28 v23.31,30.52
  Bottom 0.406: CA6V1.S 29.92,41.57 30.68,40.81 30.68,38.14 29.92,37.38 29.92,35.6 30.42,35.09 30.42,32.42 29.28,31.28 24.07,31.28 v23.31,30.52
N$7
  Top 0.406: R45.1 15.25,36.04 15.57,35.73 15.57,35.47 15.82,35.22 15.88,35.28 R41.2 16.01,35.28 16.45,35.73 16.45,35.6 18.99,35.6 IC6.9 18.99,31.41 19.88,30.52 19.97,30.61 C19.2
N$8  (via drill 0.6 pad 1.42)
  Top 0.406: R41.1 17.53,33.38 17.72,33.19 IC6.8 17.72,31.66 | 17.72,31.66 17.72,30.39 19.12,28.99 19.5,28.99 19.63,28.87 19.67,28.91 C19.1 | 17.72,31.66 v16.33,31.66 | CA6V1.E 27.38,44.87 27.31,44.94 R73.1
  Bottom 0.406: v16.33,31.66 19.88,35.22 19.88,39.66 21.28,41.06 22.3,41.06 22.93,41.69 22.93,44.23 23.19,44.49 27.12,44.49 CA6V1.E
N$10  (via drill 0.6 pad 1.27)
  Top 0.406: Q3.3 36.22,24.63 36.14,24.55 35.89,24.8 v35.89,26.45 | 3.25,21.63 8.83,21.63 11.25,24.04 13.53,24.04 14.68,25.18 17.57,25.18 v18.13,25.74 | C18.1 32.84,29.25 34.16,27.93 D13.A
  Top 0.61: D13.A 34.23,26.96 33.39,26.12 D12.A 33.39,24.37 33.47,24.3 33.81,24.63 Q3.3 37.62,24.63 38.43,25.44 | 38.43,25.44 T5.3 | C1.1 39.82,24.04 38.43,25.44 | 3.25,21.63 1.6,23.28 1.6,35.34 3.75,37.5 3.75,72.07 4.06,72.38 Q2.B
  Bottom 0.406: v18.13,25.74 18.84,26.45 v35.89,26.45
N$11
  Bottom 0.406: TRAN2.1 53.34,21.81 53.03,21.5 R120.2
N$12  (via drill 0.6 pad 1.27)
  Top 0.305: IC5.32 50.37,39.28 v51.38,38.27
  Bottom 0.406: v51.38,38.27 51.38,31.92 53.41,31.92 56.59,28.74 56.59,27.47 56.97,27.09 56.97,25.18 55.95,24.17 55.95,22.14 55.93,22.24 TRAN2.2
N$14
  Top 0.406: CA6V.E 29.03,32.68 29.66,32.04 30.55,32.04 31,31.6 R70.2
N$16
  Top 0.406: IC6.14 25.34,33.06 26.61,31.79 26.61,30.65 26.74,30.52 C23.2 27.63,30.52 28.9,29.25 28.9,25.57 29.99,24.47 D12.C 29.99,24.37 29.54,23.91 29.54,17.56 30.93,16.17 R63.2
N$17
  Top 0.406: R66.1 26.05,48.49 CA6V1.A
N$19
  Top 0.406: R32.2 15.57,43.47 13.28,45.73 13.28,49.57 9.47,53.38 9.47,62.78 10.1,63.41 10.1,63.28
  Top 0.61: 6.8,65.57 6.8,65.44 6.68,65.32
  Top 2.184: R29.1 6.8,65.57 7.31,65.57 9.6,63.28 10.1,63.28 14.04,63.28 18.36,67.6 24.73,67.6 25.7,68.57 25.7,71.82 Q4.E
N$22
  Top 0.406: R27.2 41.47,24.04 41.73,23.79 R14.1 41.67,22.2 42.36,21.5 D4.A
N$23
  Top 0.406: D1.C 36.6,17.52 38.73,19.65 D2.A
N$25
  Top 0.406: R33.2 39.5,27.91 39.38,27.79 T5.1 39.53,27.68 39.63,27.79 R27.1
N$28
  Bottom 1.27: Q4.B 14.78,71.77 14.12,72.43 Q2.E
N$33  (via drill 0.6 pad 1.42)
  Top 0.406: 23.69,19.72 23.74,19.77 Q8.3 22.3,19.85 21.79,20.36 21.79,20.49 | Q7.3 22.17,25.57 21.79,25.18 21.79,20.49 | v21.15,20.49 21.79,20.49
  Bottom 0.406: v21.15,20.49 20.9,20.49 20.47,20.05 20.47,18.73 C52.+
N$34
  Top 0.406: R37.2 47.76,15.85 48.71,16.8 49.47,16.8 49.47,17.31 | 49.47,17.31 49.47,17.44 49.5,17.41 TRAN1.4 49.5,17.54 49.47,17.56 | IC4.4 52.14,22.39 49.47,19.72 49.47,17.56 | 49.47,17.31 49.47,17.56
N$35
  Top 0.305: 54.5,49.19 52.27,49.19 52.01,49.44 49.73,49.44 49.6,49.31 49.6,48.3 IC5.10 | 54.5,49.19 J9.2 | R35.1 54.56,49.25 54.5,49.19
N$36
  Top 0.406: D2.C 35.33,19.77 35.25,19.85 35.32,19.92 Q3.1 35.32,22.2 35.06,21.94 R22.1
N$37
  Top 0.406: R63.1 30.99,14.33 31.44,13.88 | J10.6 31.44,11.09
  Top 0.61: 31.44,11.09 31.44,13.88
N$38
  Top 0.61: R64.1 33.35,11.85 J10.5
N$39  (via drill 0.6 pad 1.27)  (1 unrouted)
  Top 0.305: v40.2,42.58 41.09,42.58 41.73,41.95 43.25,41.95
  Top 0.406: R2.1 17.66,52.68 18.36,51.98 21.66,51.98 21.92,52.24 R3.2 21.98,50.77 v22.42,50.33 | 43.25,41.95 IC5.23
  Route2 0.254: 43.63,39.56 46.43,44.64
  Bottom 0.406: v22.42,50.33 24.96,52.87 33.6,52.87 35.89,50.58 35.89,46.27 39.57,42.58 v40.2,42.58
N$40
  Top 0.406: R2.2 15.82,54.78 13.79,56.81 D3.A | R39.2 20.01,44.62 19.44,45.19 R36.1 18.3,45.19 18.36,45.25 18.36,49.57 17.6,50.33 C46.+ | D5.A 6.42,29.5 7.86,30.94 C49.2
  Bottom 1.016: 6.55,50.46 C46.+
  Bottom 1.778: 6.55,33.95 6.55,50.46 6.55,53.38 9.98,56.81 D3.A
  Bottom 1.93: 6.55,33.95 R29.2 D5.A
N$41
  Top 2.54: 7.69,3.59 7.69,8.67
N$42  (via drill 0.6 pad 1.42)
  Top 0.406: v22.17,17.82 23.31,17.82 24.2,16.93 D14.C 24.76,17.23 24.96,17.44 26.49,17.44 26.74,17.18 D15.A
  Bottom 0.406: v22.17,17.82 22.19,17.82 20.54,16.17 C52.-
N$43
  Top 0.406: R18.1 34.68,51.79 35.5,52.62 L2.2
N$44
  Top 0.406: 49.5,24.42 TRAN1.1 | 49.5,24.42 49.5,24.65 49.35,24.8 | R53.2 44.78,26.2 45.54,25.44 48.46,25.44 49.47,24.42 49.5,24.42
N$45
  Top 0.406: IC4.1 55.95,21.37 56.59,20.74 59.89,20.74 60.9,19.72 60.9,17.82 60.88,17.79 TRAN3.2
N$47  (via drill 0.6 pad 1.27)
  Top 0.305: v40.71,41.19 43.12,41.19
  Top 0.406: R4.2 21.22,54.21 21.66,54.65 21.79,54.52 R12.1 21.85,55.98 v22.04,56.17 | 43.12,41.19 43.13,41.18 IC5.24
  Bottom 0.406: v22.04,56.17 22.04,51.98 21.28,51.22 21.28,49.44 21.92,48.81 23.19,48.81 23.95,49.57 23.95,50.71 25.22,51.98 33.35,51.98 35.12,50.2 35.12,45.12 39.06,41.19 v40.71,41.19
N$48
  Top 2.54: 12.64,3.72 12.64,8.8
N$49
  Top 2.54: 17.47,3.72 17.47,8.8
N$50
  Top 2.54: 22.42,3.72 22.42,8.8
N$51
  Top 2.54: 53.79,58.2 58.87,58.2
N$52
  Top 2.54: 53.79,63.28 58.87,63.28
N$54
  Top 0.406: R38.2 58.49,15.28 58.34,15.43 TRAN3.1
N$55
  Bottom 0.406: R121.2 53.39,15.91 TRAN2.4 53.39,16.78 53.41,16.8 53.41,18.2 53.5,18.28 T2.1
N$56
  Top 1.016: IC3.OUT 36.55,69.81 38.45,67.91 L1.2
  Bottom 0.406: C8.1 39.59,65.09 L1.2
N$57
  Top 0.406: R5.2 54.11,36.43 53.79,35.98 53.79,33.95 55.06,32.68 LED1.A
  Bottom 0.406: LED1.A 56.84,31.92 57.09,31.66 60.02,31.66 60.65,31.03 60.65,26.45 60.27,26.07 60.27,23.28 57.6,20.61 51.63,20.61 50.87,19.85 46.68,19.85 45.66,18.83 45.66,8.8 29.03,8.8 J10.7
N$59  (via drill 0.6 pad 1.27)
  Top 0.406: v7.69,58.59 5.79,56.68 5.79,36.87 4.26,35.34 4.26,26.84 5.53,25.57 8.83,25.57 9.72,26.45 R119.2 | v21.79,58.33 21.79,58.08 22.42,57.44 24.2,57.44 | 24.2,57.44 24.14,57.51 R74.2 | 24.2,57.44 24.33,57.32
  Bottom 0.254: D7.C 10.61,12.99 10.93,13.31
  Bottom 0.406: v7.69,58.59 8.83,59.73 21.15,59.73 21.79,59.09 v21.79,58.33
  Bottom 0.61: 9.98,14.14 9.98,13.88 9.72,14.14
  Bottom 0.813: 9.98,13.88 9.72,13.63 R119.2
  Bottom 2.54: D5.C 9.98,14.14 10.1,14.14 10.93,13.31 12.64,11.6 12.64,8.67 | 12.64,8.67 12.7,8.72 X2.4 | X2.3 12.7,3.52 12.64,3.47 12.64,8.67
N$60  (via drill 0.6 pad 1.27)
  Top 0.406: IC6.1 25.34,39.66 25.6,39.92 27,39.92 27.12,40.04 27.03,40.13 C42.1 26.78,40.13 26.49,40.42 v26.49,41.69 | R64.2 33.28,16.23 31.95,17.56 31.19,17.56 30.55,18.2 30.55,22.52 31.44,23.41 31.44,26.07 30.76,26.76 D13.C 30.76,27.14 29.79,28.11 29.79,29.88 28.65,31.03 28.65,31.15 27.5,32.3 27.5,34.2 v27.12,34.58
  Bottom 0.406: v27.12,34.58 27.12,40.93 v26.49,41.69
N$61  (via drill 3.2)  (1 unrouted)
  other vias: 61.54,3.98 2.74,3.98
N$64
  Top 0.406: R72.2 49.73,28.74 49.86,28.61 49.98,28.61 50.24,28.87 LRED.A
N$65  (via drill 0.6 pad 1.42)
  Top 0.406: IC4.2 IC4.3 | IC4.2 54.68,23.66 | IC4.2 54.68,20.99 55.95,19.72 58.75,19.72 59.89,18.58 59.89,16.17 v60.52,15.53
  Bottom 0.406: v60.52,15.53 60.48,15.53 | R6.2 50.62,18.2 52.01,19.6 60.27,19.6 60.9,18.96 60.9,15.91 v60.52,15.53 | v60.52,15.53 60.52,15.66 60.1,16.08 T2.3
N$66
  Top 0.406: 50.62,26.71 LGREEN.A R71.2
N$67  (via drill 0.6 pad 1.27)
  Top 0.406: Q3.2 37.22,21.06 v37.03,20.87 | v17.47,28.49 16.2,28.49 v14.04,30.65
  Bottom 0.406: v37.03,20.87 37.03,27.6 36.39,28.23 28.95,28.23 28.19,27.47 26.67,27.47 25.9,28.23 17.72,28.23 v17.47,28.49 | v14.04,30.65 11.5,30.65 8.33,33.57 8.33,36.36 9.09,37.12 9.98,37.12 12.9,40.04 R10.1
N$68  (via drill 0.6 pad 1.27)
  Top 0.406: 53.84,63.18 X1.4 53.18,63.84 v47.44,63.84
  Bottom 0.406: C11.2 57.64,67.82 57.35,68.11 55.77,68.11 55.72,68.06 55.01,68.06 54.96,68.11 54.91,68.11 | C12.1 46.49,64.8 v47.44,63.84
  Bottom 2.184: X1.4 53.87,63.21 53.92,63.16 53.97,63.21 54.91,63.21 X1.3
  Bottom 2.54: 54.91,63.21 54.91,68.11 B1.~2
N$69
  Bottom 0.254: 57.13,58.62 57.6,58.71 X1.1
  Bottom 0.406: C6.1 57.13,58.62 56.71,58.2 | C5.1 46.51,69.09 46.93,69.51 48.74,69.51 48.86,69.38 48.97,69.38
  Bottom 2.184: X1.2 53.92,58.2 | X1.2 51.25,58.2 50.11,59.35 50.11,65.19 48.97,66.33 48.97,69.38 48.97,71.01 49.88,71.92 B1.~1 | X1.2 X1.1 60.14,58.2
N$100
  Top 0.305: R92.2 40.08,14.14 39.82,13.88
  Top 0.406: D4.C 42.44,17.9 | 39.82,13.88 39.19,13.25 J10.3 | 41.85,17.44 41.85,16.68 40.46,15.28 40.46,14.39 40.2,14.14 R92.2
  Top 0.61: D4.C 42.31,17.9 41.85,17.44
N$112
  Bottom 0.813: Q1.D 24.96,61.25 24.71,61 J1.2
N$115  (via drill 0.6 pad 1.27)
  Top 0.305: v30.42,57.32 34.11,57.32 37.03,54.39 37.03,52.49 37.41,52.11 39.31,52.11 40.46,53.25 47.19,53.25 48.71,51.73 48.71,48.43
  Top 0.406: 48.71,48.43 48.77,48.37 IC5.11
  Bottom 0.406: Q1.G 26.49,62.52 27.25,61.76 27.25,61 29.47,58.77 | 29.47,58.77 29.54,58.71 | 29.47,58.77 R7.1 29.6,58.14 v30.42,57.32
N$125  (via drill 0.6 pad 1.27)
  Top 0.305: IC5.20 46.19,44.38 v46.55,44.74
  Bottom 0.305: C15.2 46.81,46.39 46.55,46.14 v46.55,44.74
N$144
  Top 0.406: R9.1 44.65,13.5 45.79,12.36 45.79,8.67 45.03,7.91 37.54,7.91 36.65,8.8 J10.4
RST  (via drill 0.6 pad 1.27)
  Top 0.305: IC5.29 47.97,40.95 48.33,41.31 50.24,41.31 v51.76,39.79
  Top 0.406: R8.1 56.21,35.22 56.84,34.58 56.84,33.31 57.22,32.93 SV2.5 58.87,32.93
  Bottom 0.406: v51.76,39.79 51.76,39.54 53.03,38.27 53.03,34.2 54.05,33.19 58.49,33.19 SV2.5
RXD  (via drill 0.6 pad 1.27)
  Top 0.305: IC5.30 48.71,39.63 48.71,38.14 v48.33,37.63
  Top 0.406: TRAN3.4 58.26,24.14 | 58.34,24.3 58.36,24.3 | TRAN3.4 58.34,24.3 | 58.34,24.3 58.24,24.3 | LGREEN.C 55.32,26.71 v55.82,26.2 | v55.82,26.2 55.93,26.1 57.58,26.1 58.36,25.31 58.36,24.42 58.34,24.4 TRAN3.4 | R54.2 55.44,26.71 v55.82,26.2
  Bottom 0.406: v48.33,37.63 48.33,36.87 49.47,35.73 49.47,23.53 52.01,23.53 52.01,26.2 v55.82,26.2
SCK  (via drill 0.6 pad 1.27)
  Top 0.305: IC5.17 43,46.78 | v41.98,50.08 42.11,50.08 43.25,48.93 43.25,46.77 IC5.17 | 43.12,46.77 43.13,46.78 IC5.17
  Bottom 0.406: v41.98,50.08 41.85,50.08 41.85,53.63 59.51,53.63 60.65,52.49 60.65,46.39 58.75,44.49 SV2.1
SCK_DA
  Top 0.305: U$9.3 38.17,40.3 37.66,40.81 37.66,42.84 36.77,43.73 36.77,46.77 U$16.3 39.7,46.77 40.08,47.16 40.08,50.97 40.97,51.85 46.55,51.85 47.19,51.22 47.19,48.3
  Top 0.406: 47.19,48.3 IC5.13
SDI
  Top 0.305: U$16.4 36.14,48.04 36.14,43.35 36.9,42.58 U$9.4 | 39.19,48.04 39.19,50.97 40.71,52.49 46.81,52.49 47.95,51.35 47.95,48.43
  Top 0.406: U$16.4 39.19,48.04 | IC5.12 47.93,48.27 47.95,48.3 47.95,48.43
TXD  (via drill 0.6 pad 1.27)
  Top 0.305: IC5.31 49.57,38.17 v49.86,38.01
  Top 0.406: 53.54,28.99 53.44,28.89 LRED.C 53.41,28.87 53.28,28.99 53.16,28.99 53.03,29.12 v53.03,30.65 | TRAN1.2 46.96,22.11 47.19,21.88 49.98,21.88 50.74,22.64 v50.74,24.93
  Bottom 0.406: 49.73,38.27 v49.86,38.01 50.36,37.63 50.36,30.65 50.74,30.65 | 50.74,30.65 v53.03,30.65 | v50.74,24.93 50.74,30.65
V+  (via drill 0.6 pad 1.27)
  Top 0.254: 40.2,17.69 39.82,17.56 D1.A
  Top 0.406: C1.2 39.91,21.79 40.33,21.37 40.33,17.82 40.2,17.69 39.95,17.44 40,17.39 | R4.1 19.7,56.11 19.25,56.55 16.96,56.55 16.45,57.06 16.45,59.09 14.87,60.68 | IC12.IN 13.41,22.77 16.86,19.32 v16.86,18.5 | D1.A 40,17.23 v36.52,13.75
  Top 0.813: R10.2 11.12,54.14 11.12,59.6 11.88,60.36 14.55,60.36 14.87,60.68 17.72,63.54 18.74,63.54 18.79,63.59 18.84,63.54 J1.1
  Bottom 0.406: IC12.IN 12.77,22.77 11.25,24.3 11.25,28.36 10.61,28.99 8.96,28.99 8.45,28.49 8.45,26.33 7.82,25.69 2.48,25.69 | 36.57,13.7 v36.52,13.75 35.35,14.92 18.84,14.92 16.86,16.9 v16.86,18.5 | B1.+ 44.75,71.87 44.45,71.56 44.45,69.53 44.81,69.16 C5.2 44.78,69 44.45,68.67 44.45,67.14 44.79,66.8 C12.2
  Bottom 0.61: 26.49,67.22 26.49,66.84 26.36,66.71
  Bottom 0.813: 7.95,68.87 7.95,68.62 7.82,68.75 | 2.48,44.36 3.12,44.36 | 18.84,67.22 18.84,66.94 18.87,66.92 18.87,63.56 18.84,63.54 | 18.84,63.54 18.79,63.49 | 18.84,63.54 J1.1
  Bottom 1.422: 6.6,68.87 Q2.C | C9.+ 46.81,59.75 41.96,64.6 41.96,71.92
  Bottom 1.676: 31.49,67.22 31.49,67.4 31.47,67.42 IC3.IN
  Bottom 1.778: 13.36,67.22 13.36,67.09 13.41,67.04 D3.C
  Bottom 2.54: 2.48,53.38 2.48,44.36 2.48,25.69 2.48,11.47 5.15,8.8 7.56,8.8 7.59,8.78 X2.2 X2.1 7.69,3.72 | 2.48,53.38 2.48,53.51 | 7.92,68.87 6.6,68.87 5.41,68.87 2.48,65.95 2.48,53.38 | 7.92,68.87 7.95,68.87 | 20.26,67.22 18.84,67.22 13.36,67.22 9.57,67.22 7.92,68.87 | 20.26,67.22 26.49,67.22 31.49,67.22 32.2,67.22 32.2,67.25 33.52,68.57 37.38,68.57 40.74,71.92 41.96,71.92 B1.+ | 20.26,67.22 Q4.C
VCC_RS485  (via drill 0.6 pad 1.27)
  Top 0.406: R37.1 49.66,14.58 v48.46,13.37 | IC4.8 55.95,15.91 56.59,15.28 R38.1 56.65,13.95 v56.08,13.37 57.22,13.37 J7.1 57.22,10.96 58.63,9.55 C13.2
  Bottom 0.406: 48.97,13.37 v48.46,13.37 48.46,13.5 48.52,13.5 R121.1 | 48.97,13.37 53.41,13.37 | 53.41,13.37 v56.08,13.37 | 48.97,13.37 48.91,13.43 | 53.41,13.37 53.39,13.37 | R121.1 R6.1 | R121.1 48.59,15.91
VOUT
  Top 0.406: U$16.8 30.04,44.23 29.28,43.47 29.28,43.09 28.9,42.71 26.87,42.71 26.74,42.84 25.47,42.84 25.09,42.46 25.09,41.44 24.71,41.31 | IC6.3 22.8,39.66 23.06,39.92 23.31,39.92 24.71,41.31 | 24.71,41.31 R69.2
ZAS_ON_OFF  (via drill 0.6 pad 1.27)
  Top 0.406: 42.04,13.69 R92.1 42.04,14.2 42.74,14.9 v42.74,15.79 | v53.41,42.2 53.16,41.95 52.01,41.95 51.98,41.98 IC5.2
  Bottom 0.406: v53.41,42.2 53.16,41.95 49.98,41.95 47.19,39.15 47.19,36.23 48.46,34.96 48.46,27.22 47.19,25.95 44.01,25.95 43.12,25.06 43.12,16.17 v42.74,15.79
